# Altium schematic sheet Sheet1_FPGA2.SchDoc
size A2
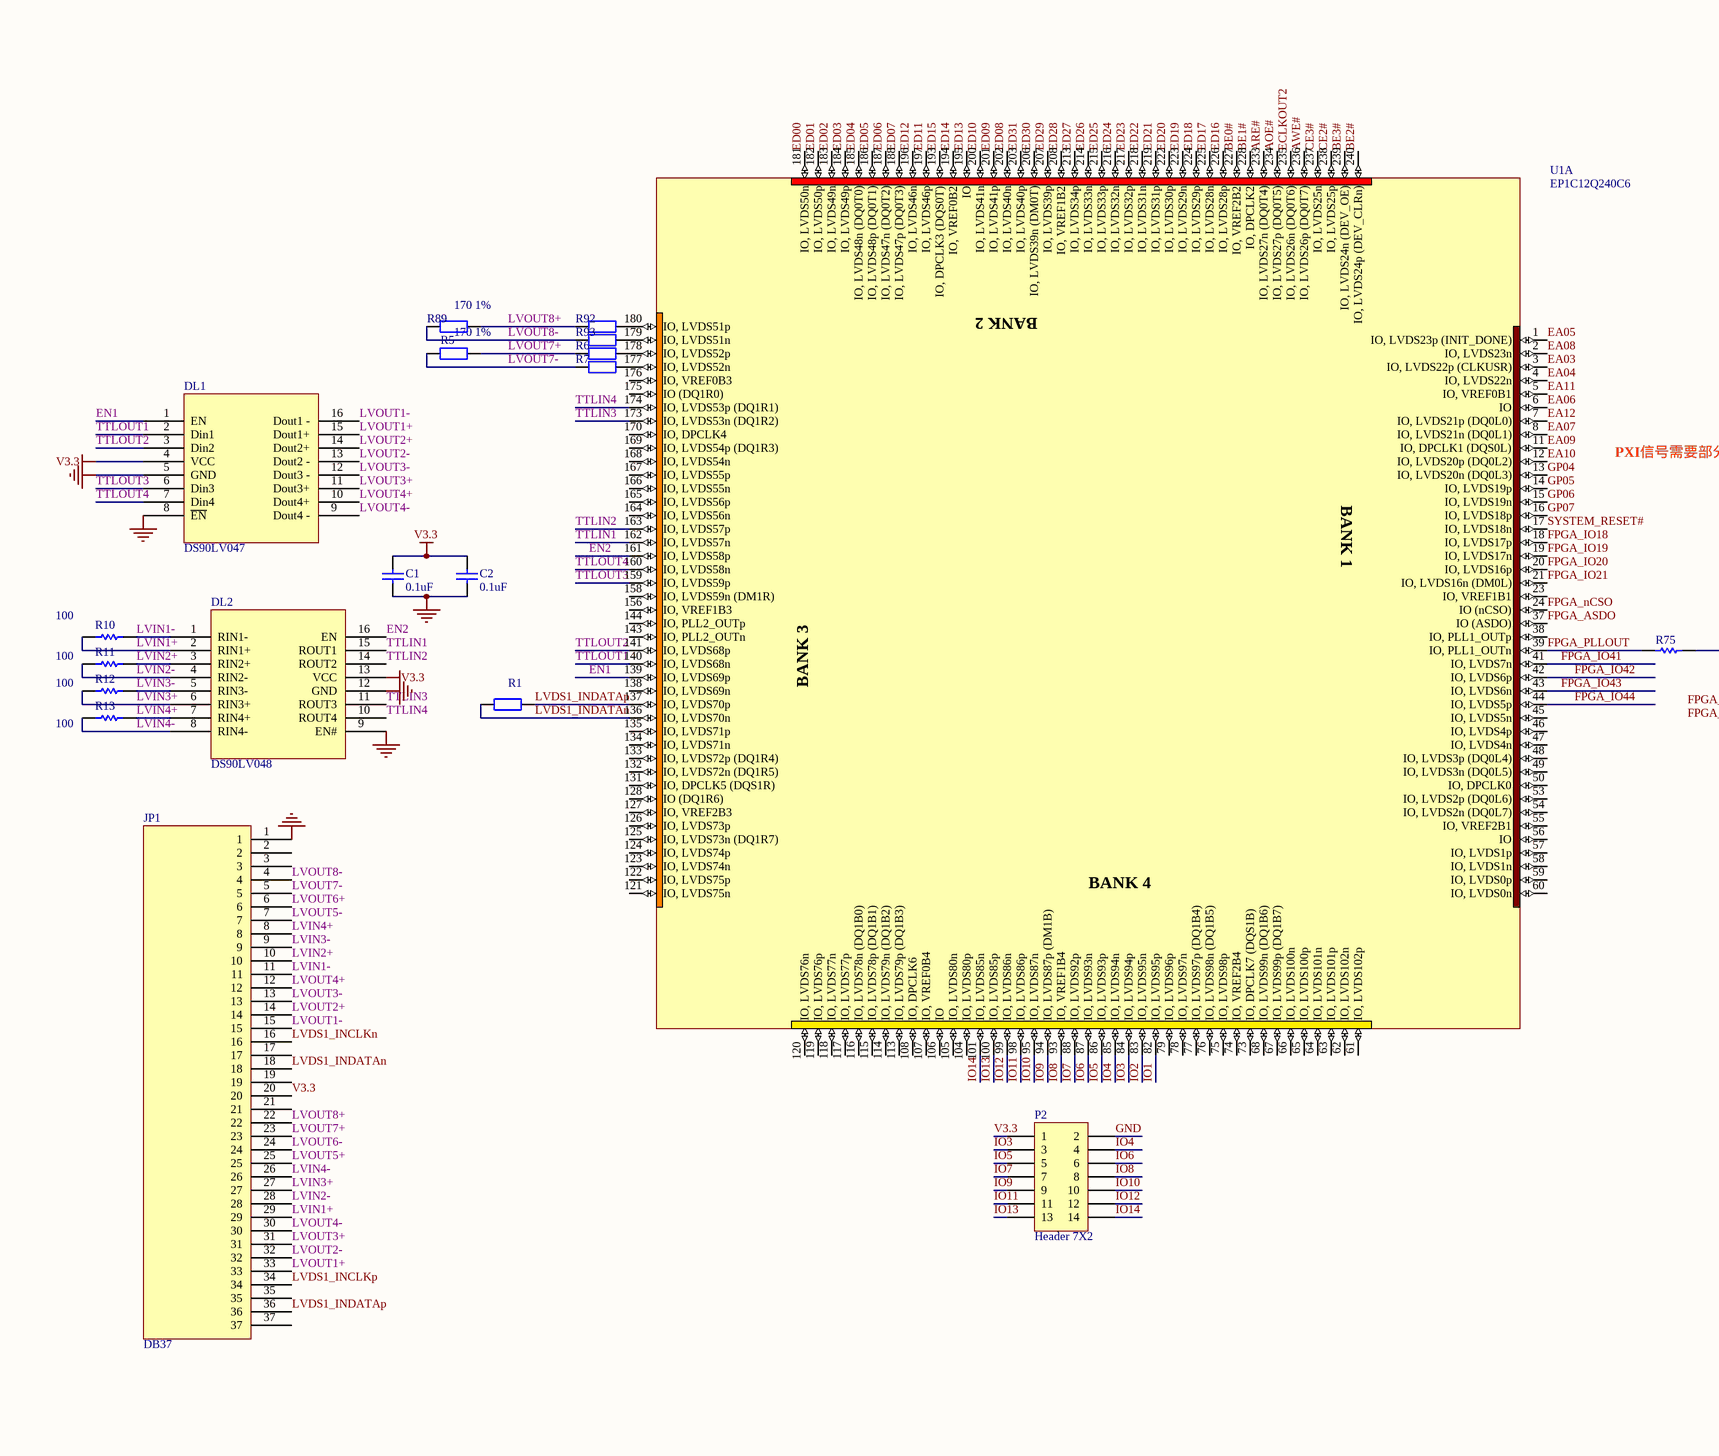
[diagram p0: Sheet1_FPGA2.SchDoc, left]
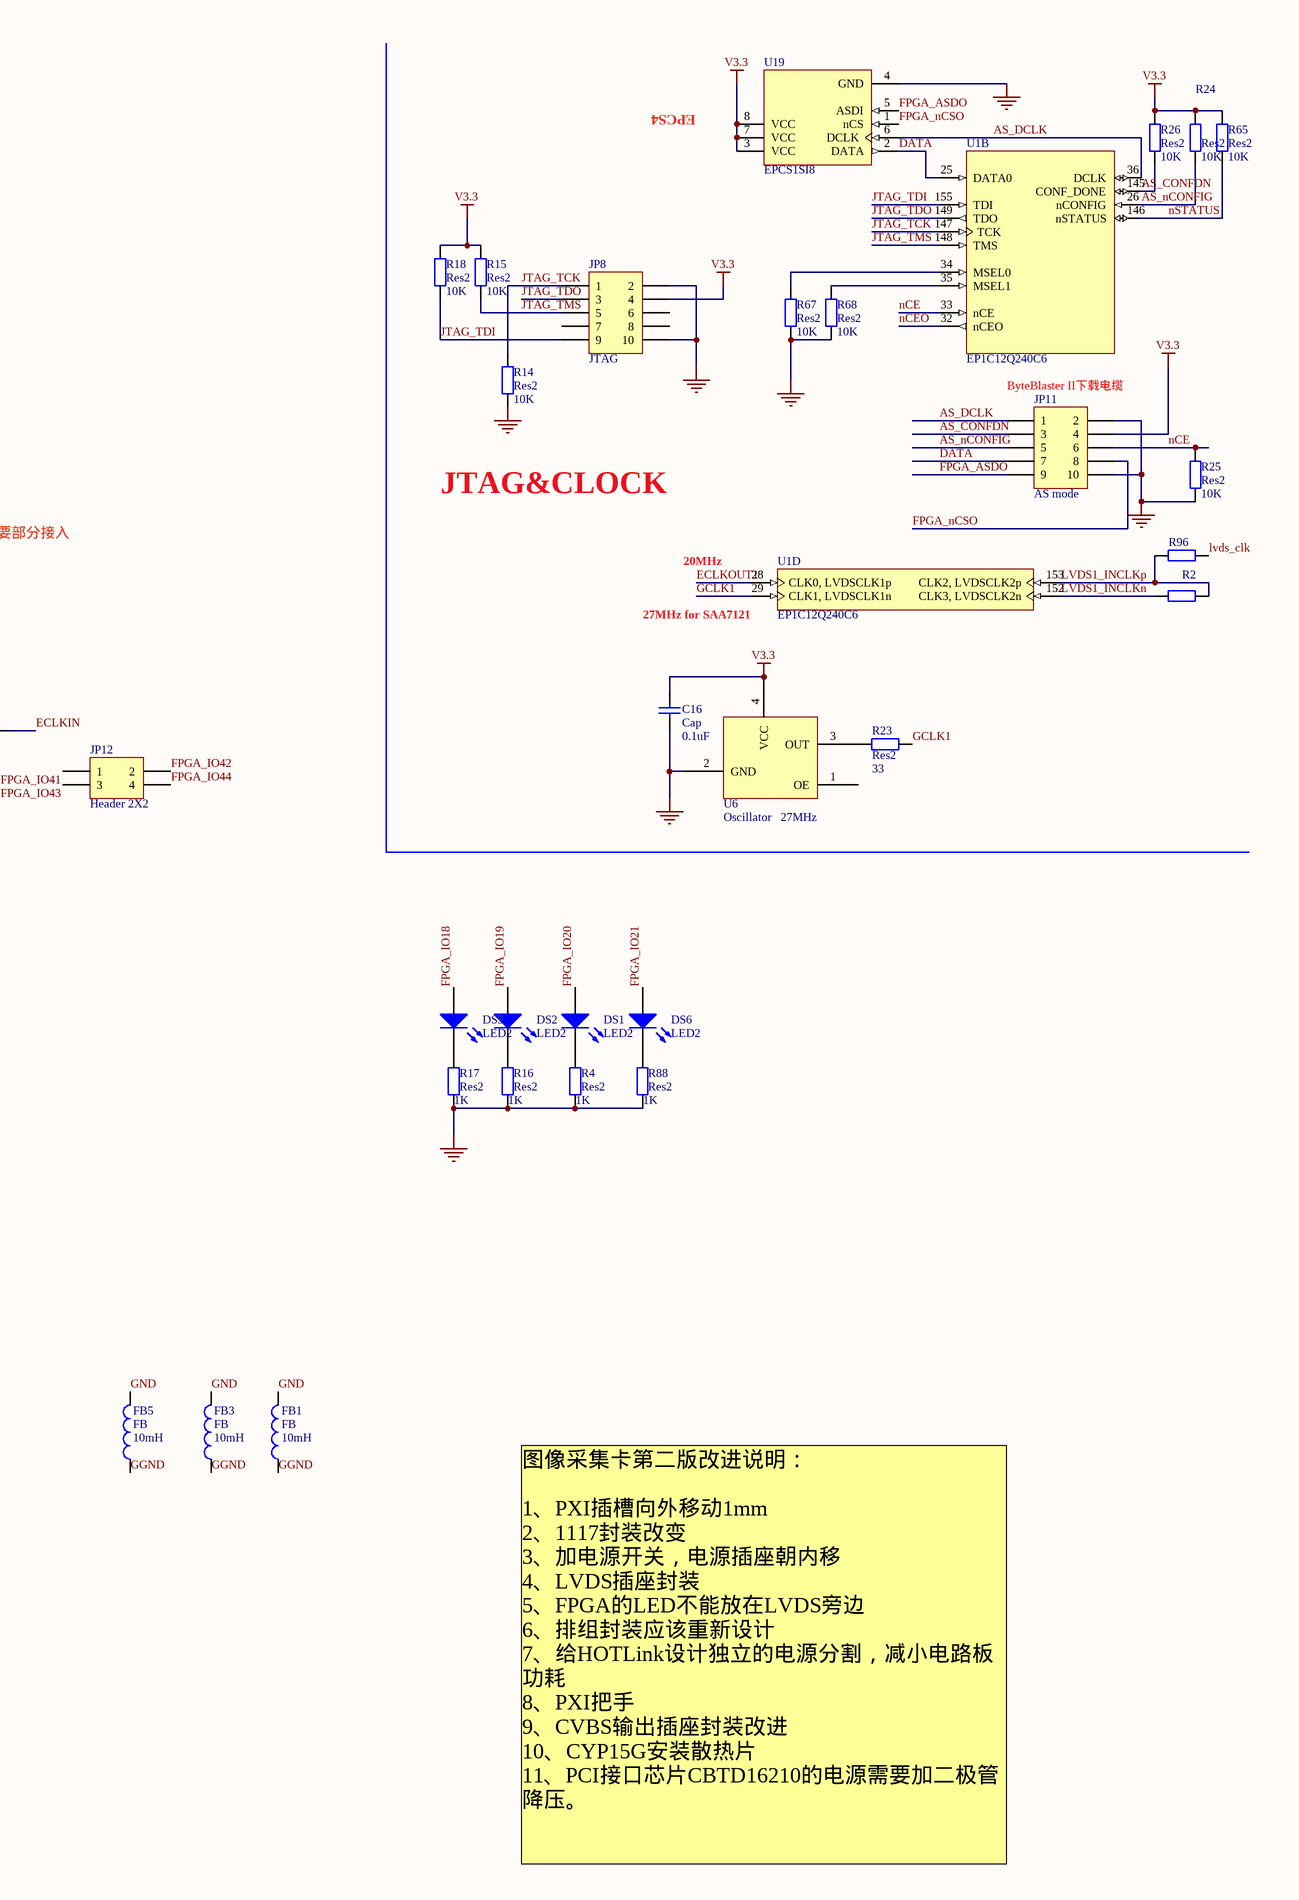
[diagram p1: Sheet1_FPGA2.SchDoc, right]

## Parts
C1  0.1uF  [C1608-0603]
C2  0.1uF  [C1608-0603]
C16  Cap  value 0.1uF  [C1608-0603]
DL1  DS90LV047  [SO-16]
DL2  DS90LV048  [SO-16]
DS1  LED2  [SMD _LED]
DS2  LED2  [SMD _LED]
DS3  LED2  [SMD _LED]
DS6  LED2  [SMD _LED]
FB1  FB  value 10mH  [C1608-0603]
FB3  FB  value 10mH  [C1608-0603]
FB5  FB  value 10mH  [C1608-0603]
JP1  DB37  [DB37]
JP8  JTAG  [HDR2X5]
JP11  AS mode  [HDR2X5]
JP12  Header 2X2  [HDR2X2]
P2  Header 7X2  [HDR2X7]
R1  Res2  [C1608-0603]  (value not drawn)
R2  Res2  [C1608-0603]  (value not drawn)
R4  Res2  value 1K  [C1608-0603]
R5  value 170 1%  [C1608-0603]  (hidden comment: Res2)
R6  Res2  [C1608-0603]  (value not drawn)
R7  Res2  [C1608-0603]  (value not drawn)
R10  value 100  [CR1608-0603]
R11  value 100  [CR1608-0603]
R12  value 100  [CR1608-0603]
R13  value 100  [CR1608-0603]
R14  Res2  value 10K  [C1608-0603]
R15  Res2  value 10K  [C1608-0603]
R16  Res2  value 1K  [C1608-0603]
R17  Res2  value 1K  [C1608-0603]
R18  Res2  value 10K  [C1608-0603]
R23  Res2  value 33  [C1608-0603]
R24  Res2  value 10K  [C1608-0603]
R25  Res2  value 10K  [C1608-0603]
R26  Res2  value 10K  [C1608-0603]
R65  Res2  value 10K  [C1608-0603]
R67  Res2  value 10K  [C1608-0603]
R68  Res2  value 10K  [C1608-0603]
R75  Res1  [CR1608-0603]  (value not drawn)
R88  Res2  value 1K  [C1608-0603]
R89  value 170 1%  [C1608-0603]  (hidden comment: Res2)
R92  Res2  [C1608-0603]  (value not drawn)
R93  Res2  [C1608-0603]  (value not drawn)
R96  Res2  [C1608-0603]  (value not drawn)
U1  EP1C12Q240C6  [PQFP240]  (parts A,B,D of 4)
U6  Oscillator   27MHz  [OSC]
U19  EPCS1SI8  [SOIC8]

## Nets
GND: C1.2 C2.2 C16.1 DL1.5(GND) DL1.8(~{EN}) DL2.9(EN#) DL2.12(GND) FB1.2 FB3.2 FB5.2 JP1.1 JP8.2 JP8.10 JP11.2 JP11.10 P2.2 R4.2 R14.1 R16.2 R17.2 R25.1 R67.1 R68.1 R88.2 U6.2(GND) U19.4(GND)
V3.3: C1.1 C2.1 C16.2 DL1.4(VCC) DL2.13(VCC) JP1.20 JP8.4 JP11.4 P2.1 R15.2 R18.2 R24.2 R26.2 R65.2 U6.4(VCC) U19.3(VCC) U19.7(VCC) U19.8(VCC)
AOE#: U1.234(IO,_LVDS27p_(DQ0T5))
ARE#: U1.233(IO,_LVDS27n_(DQ0T4))
AS_CONFDN: JP11.3 R26.1 U1.145(CONF_DONE)
AS_DCLK: JP11.1 U1.36(DCLK) U19.6(DCLK)
AS_nCONFIG: JP11.5 R24.1 U1.26(nCONFIG)
AWE#: U1.236(IO,_LVDS26p_(DQ0T7))
BE0#: U1.227(IO,_VREF2B2)
BE1#: U1.228(IO,_DPCLK2)
BE2#: U1.240(IO,_LVDS24p_(DEV_CLRn))
BE3#: U1.239(IO,_LVDS24n_(DEV_OE))
CE2#: U1.238(IO,_LVDS25p)
CE3#: U1.237(IO,_LVDS25n)
DATA: JP11.7 U1.25(DATA0) U19.2(DATA)
EA03: U1.3(IO,_LVDS22p_(CLKUSR))
EA04: U1.4(IO,_LVDS22n)
EA05: U1.1(IO,_LVDS23p_(INIT_DONE))
EA06: U1.6(IO)
EA07: U1.8(IO,_LVDS21n_(DQ0L1))
EA08: U1.2(IO,_LVDS23n)
EA09: U1.11(IO,_DPCLK1_(DQS0L))
EA10: U1.12(IO,_LVDS20p_(DQ0L2))
EA11: U1.5(IO,_VREF0B1)
EA12: U1.7(IO,_LVDS21p_(DQ0L0))
ECLKIN: R75.2
ECLKOUT1: U1.28(CLK0,_LVDSCLK1p)
ECLKOUT2: U1.235(IO,_LVDS26n_(DQ0T6))
ED00: U1.181(IO,_LVDS50n)
ED01: U1.182(IO,_LVDS50p)
ED02: U1.183(IO,_LVDS49n)
ED03: U1.184(IO,_LVDS49p)
ED04: U1.185(IO,_LVDS48n_(DQ0T0))
ED05: U1.186(IO,_LVDS48p_(DQ0T1))
ED06: U1.187(IO,_LVDS47n_(DQ0T2))
ED07: U1.188(IO,_LVDS47p_(DQ0T3))
ED08: U1.202(IO,_LVDS40n)
ED09: U1.201(IO,_LVDS41p)
ED10: U1.200(IO,_LVDS41n)
ED11: U1.197(IO,_LVDS46p)
ED12: U1.196(IO,_LVDS46n)
ED13: U1.195(IO)
ED14: U1.194(IO,_VREF0B2)
ED15: U1.193(IO,_DPCLK3_(DQS0T))
ED16: U1.226(IO,_LVDS28p)
ED17: U1.225(IO,_LVDS28n)
ED18: U1.224(IO,_LVDS29p)
ED19: U1.223(IO,_LVDS29n)
ED20: U1.222(IO,_LVDS30p)
ED21: U1.219(IO,_LVDS31p)
ED22: U1.218(IO,_LVDS31n)
ED23: U1.217(IO,_LVDS32p)
ED24: U1.216(IO,_LVDS32n)
ED25: U1.215(IO,_LVDS33p)
ED26: U1.214(IO,_LVDS33n)
ED27: U1.213(IO,_LVDS34p)
ED28: U1.208(IO,_VREF1B2)
ED29: U1.207(IO,_LVDS39p)
ED30: U1.206(IO,_LVDS39n_(DM0T))
ED31: U1.203(IO,_LVDS40p)
EN1: DL1.1(EN) U1.139(IO,_LVDS69p)
EN2: DL2.16(EN) U1.161(IO,_LVDS58p)
FPGA_ASDO: JP11.9 U1.37(IO_(ASDO)) U19.5(ASDI)
FPGA_IO18: DS3.1(A) U1.18(IO,_LVDS17p)
FPGA_IO19: DS2.1(A) U1.19(IO,_LVDS17n)
FPGA_IO20: DS1.1(A) U1.20(IO,_LVDS16p)
FPGA_IO21: DS6.1(A) U1.21(IO,_LVDS16n_(DM0L))
FPGA_IO41: JP12.1 U1.41(IO,_LVDS7n)
FPGA_IO42: JP12.2 U1.42(IO,_LVDS6p)
FPGA_IO43: JP12.3 U1.43(IO,_LVDS6n)
FPGA_IO44: JP12.4 U1.44(IO,_LVDS5p)
FPGA_nCSO: JP11.8 U1.24(IO_(nCSO)) U19.1(nCS)
FPGA_PLLOUT: R75.1 U1.39(IO,_PLL1_OUTn)
GCLK1: R23.2 U1.29(CLK1,_LVDSCLK1n)
GGND: FB1.1 FB3.1 FB5.1
GP04: U1.13(IO,_LVDS20n_(DQ0L3))
GP05: U1.14(IO,_LVDS19p)
GP06: U1.15(IO,_LVDS19n)
GP07: U1.16(IO,_LVDS18p)
IO1: U1.82(IO,_LVDS95p)
IO2: U1.83(IO,_LVDS95n)
IO3: P2.3 U1.84(IO,_LVDS94p)
IO4: P2.4 U1.85(IO,_LVDS94n)
IO5: P2.5 U1.86(IO,_LVDS93p)
IO6: P2.6 U1.87(IO,_LVDS93n)
IO7: P2.7 U1.88(IO,_LVDS92p)
IO8: P2.8 U1.93(IO,_VREF1B4)
IO9: P2.9 U1.94(IO,_LVDS87p_(DM1B))
IO10: P2.10 U1.95(IO,_LVDS87n)
IO11: P2.11 U1.98(IO,_LVDS86p)
IO12: P2.12 U1.99(IO,_LVDS86n)
IO13: P2.13 U1.100(IO,_LVDS85p)
IO14: P2.14 U1.101(IO,_LVDS85n)
JTAG_TCK: JP8.1 R14.2 U1.147(TCK)
JTAG_TDI: JP8.9 R18.1 U1.155(TDI)
JTAG_TDO: JP8.3 U1.149(TDO)
JTAG_TMS: JP8.5 R15.1 U1.148(TMS)
LVDS1_INCLKn: JP1.16 R2.1 U1.152(CLK3,_LVDSCLK2n)
LVDS1_INCLKp: JP1.34 R2.2 R96.1 U1.153(CLK2,_LVDSCLK2p)
LVDS1_INDATAn: JP1.18 R1.1 U1.136(IO,_LVDS70n)
LVDS1_INDATAp: JP1.36 R1.2 U1.137(IO,_LVDS70p)
lvds_clk: R96.2
LVIN1+: DL2.2(RIN1+) JP1.29 R10.2
LVIN1-: DL2.1(RIN1-) JP1.11 R10.1
LVIN2+: DL2.3(RIN2+) JP1.10 R11.1
LVIN2-: DL2.4(RIN2-) JP1.28 R11.2
LVIN3+: DL2.6(RIN3+) JP1.27 R12.2
LVIN3-: DL2.5(RIN3-) JP1.9 R12.1
LVIN4+: DL2.7(RIN4+) JP1.8 R13.1
LVIN4-: DL2.8(RIN4-) JP1.26 R13.2
LVOUT1+: DL1.15(Dout1+) JP1.33
LVOUT1-: DL1.16(Dout1_-) JP1.15
LVOUT2+: DL1.14(Dout2+) JP1.14
LVOUT2-: DL1.13(Dout2_-) JP1.32
LVOUT3+: DL1.11(Dout3+) JP1.31
LVOUT3-: DL1.12(Dout3_-) JP1.13
LVOUT4+: DL1.10(Dout4+) JP1.12
LVOUT4-: DL1.9(Dout4_-) JP1.30
LVOUT5+: JP1.25
LVOUT5-: JP1.7
LVOUT6+: JP1.6
LVOUT6-: JP1.24
LVOUT7+: JP1.23 R5.2 R6.1
LVOUT7-: JP1.5 R5.1 R7.1
LVOUT8+: JP1.22 R89.2 R92.1
LVOUT8-: JP1.4 R89.1 R93.1
nCE: JP11.6 R25.2 U1.33(nCE)
nCEO: U1.32(nCEO)
nSTATUS: R65.1 U1.146(nSTATUS)
SYSTEM_RESET#: U1.17(IO,_LVDS18n)
TTLIN1: DL2.15(ROUT1) U1.162(IO,_LVDS57n)
TTLIN2: DL2.14(ROUT2) U1.163(IO,_LVDS57p)
TTLIN3: DL2.11(ROUT3) U1.173(IO,_LVDS53n_(DQ1R2))
TTLIN4: DL2.10(ROUT4) U1.174(IO,_LVDS53p_(DQ1R1))
TTLOUT1: DL1.2(Din1) U1.140(IO,_LVDS68n)
TTLOUT2: DL1.3(Din2) U1.141(IO,_LVDS68p)
TTLOUT3: DL1.6(Din3) U1.159(IO,_LVDS59p)
TTLOUT4: DL1.7(Din4) U1.160(IO,_LVDS58n)
NetDS1_2: DS1.2(K) R4.1
NetDS2_2: DS2.2(K) R16.1
NetDS3_2: DS3.2(K) R17.1
NetDS6_2: DS6.2(K) R88.1
NetR6_2: R6.2 U1.178(IO,_LVDS52p)
NetR7_2: R7.2 U1.177(IO,_LVDS52n)
NetR23_1: R23.1 U6.3(OUT)
NetR67_2: R67.2 U1.34(MSEL0)
NetR68_2: R68.2 U1.35(MSEL1)
NetR92_2: R92.2 U1.180(IO,_LVDS51p)
NetR93_2: R93.2 U1.179(IO,_LVDS51n)

Not connected (* = marked no-connect by the designer): JP1 2 3 17 19 21 35 37; JP8 6 7 8; U1 23(IO,_VREF1B1) 38(IO,_PLL1_OUTp) 45(IO,_LVDS5n) 46(IO,_LVDS4p) 47(IO,_LVDS4n) 48(IO,_LVDS3p_(DQ0L4)) 49(IO,_LVDS3n_(DQ0L5)) 50(IO,_DPCLK0) 53(IO,_LVDS2p_(DQ0L6)) 54(IO,_LVDS2n_(DQ0L7)) 55(IO,_VREF2B1) 56(IO) 57(IO,_LVDS1p) 58(IO,_LVDS1n) 59(IO,_LVDS0p) 60(IO,_LVDS0n) 61(IO,_LVDS102p) 62(IO,_LVDS102n) 63(IO,_LVDS101p) 64(IO,_LVDS101n) 65(IO,_LVDS100p) 66(IO,_LVDS100n) 67(IO,_LVDS99p_(DQ1B7)) 68(IO,_LVDS99n_(DQ1B6)) 73(IO,_DPCLK7_(DQS1B)) 74(IO,_VREF2B4) 75(IO,_LVDS98p) 76(IO,_LVDS98n_(DQ1B5)) 77(IO,_LVDS97p_(DQ1B4)) 78(IO,_LVDS97n) 79(IO,_LVDS96p) 104(IO,_LVDS80p) 105(IO,_LVDS80n) 106(IO) 107(IO,_VREF0B4) 108(IO,_DPCLK6) 113(IO,_LVDS79p_(DQ1B3)) 114(IO,_LVDS79n_(DQ1B2)) 115(IO,_LVDS78p_(DQ1B1)) 116(IO,_LVDS78n_(DQ1B0)) 117(IO,_LVDS77p) 118(IO,_LVDS77n) 119(IO,_LVDS76p) 120(IO,_LVDS76n) 121(IO,_LVDS75n) 122(IO,_LVDS75p) 123(IO,_LVDS74n) 124(IO,_LVDS74p) 125(IO,_LVDS73n_(DQ1R7)) 126(IO,_LVDS73p) 127(IO,_VREF2B3) 128(IO_(DQ1R6)) 131(IO,_DPCLK5_(DQS1R)) 132(IO,_LVDS72n_(DQ1R5)) 133(IO,_LVDS72p_(DQ1R4)) 134(IO,_LVDS71n) 135(IO,_LVDS71p) 138(IO,_LVDS69n) 143(IO,_PLL2_OUTn) 144(IO,_PLL2_OUTp) 156(IO,_VREF1B3) 158(IO,_LVDS59n_(DM1R)) 164(IO,_LVDS56n) 165(IO,_LVDS56p) 166(IO,_LVDS55n) 167(IO,_LVDS55p) 168(IO,_LVDS54n) 169(IO,_LVDS54p_(DQ1R3)) 170(IO,_DPCLK4) 175(IO_(DQ1R0)) 176(IO,_VREF0B3); U6 1(OE)

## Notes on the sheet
- EPCS4
- (near JP11) ByteBlaster II下载电缆
- JTAG&CLOCK
- PXI信号需要部分接入
- 20MHz
- (near U1) 27MHz for SAA7121
- 图像采集卡第二版改进说明：
  1、PXI插槽向外移动1mm
  2、1117封装改变
  3、加电源开关，电源插座朝内移
  4、LVDS插座封装
  5、FPGA的LED不能放在LVDS旁边
  6、排组封装应该重新设计
  7、给HOTLink设计独立的电源分割，减小电路板功耗
  8、PXI把手
  9、CVBS输出插座封装改进
  10、CYP15G安装散热片
  11、PCI接口芯片CBTD16210的电源需要加二极管降压。

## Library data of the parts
C1 C2 = Cap: Capacitor; Manufacturer: Generic Components; Class: Passive; Value: 100pF
C16 = Cap: Capacitor
DS1-DS3 DS6 = LED2: Typical RED, GREEN, YELLOW, AMBER GaAs LED
FB1 FB3 FB5 = Inductor
JP8 JP11 = Header 5X2: Header, 5-Pin, Dual row
JP12 = Header 2X2: Header, 2-Pin, Dual row
P2 = Header 7X2: Header, 7-Pin, Dual row
R1 R2 R96 = Res2: Resistor; Value: 100 1%
R4-R6 R14-R18 R23-R26 R65 R67 R68 R88 R89 R92 = Res2: Resistor
R7 R93 = Res2: Resistor; Value: 120  1%
R10-R13 = Res1: Resistor; Manufacturer: Generic Components; Class: Passive
R75 = Res1: Resistor; Value: 33
U1 = EP1C12Q240C6: Cyclone Family, 1.5V FPGA, 173 I/O Pins, 2 x PLLs, Commercial Grade, Speed Grade 6; Package Information: Latest Revision: ver11.0, Feb-2003; Code - JEDEC: MS-029-GA
U6 = Oscillator
U19 = EPCS1SI8: EPCS1 Series, In-system programmable 3.3V configuration device, 8-Pin SOIC, 1-Megabit, Industrial Grade; Package Information: Latest Revision: ver11.0, Feb-2003; Serially configures: Cyclone FPGAs; Code - JEDEC: MS-012-AA; Code - IPC: SO8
